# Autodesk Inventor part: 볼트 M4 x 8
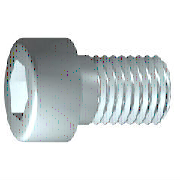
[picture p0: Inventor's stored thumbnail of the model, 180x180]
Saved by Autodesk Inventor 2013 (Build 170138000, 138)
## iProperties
IsCustomPart: 0
Created: 2012-02
Part Number: 볼트 M4 x 8
Material: 스테인리스강
Description: 6각 소켓 머리 캡 나사
Document SubType Name: Modeling
Standard: ISO 4762
Designer: mduedu
Standard Revision: Fourth edition 2004-03-01
Standards Organization: ISO
Language: ko-KR
Size Designation: M4 x 8
Categories: <MemberInstance><Categories><Category DisplayName="조임쇠" InternalName="e4da775c-781d-43d5-af7c-5136215cf5a6" Mnemonic="FSTN"><Category DisplayName="볼트" InternalN
Density: 7.75 g/cm^3
Author: mduedu
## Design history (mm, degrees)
sketch "스케치1"
  geometry: L1 (-1, 0)-(8, 0); L2 (8, 0)-(8, 2); L3 (8, 2)-(1.75, 2); L4 (1.75, 2)-(1.32, 2); L5 (1.32, 2)-(0, 2); L6 (0, 2)-(0, 3.5); L7 (0, 3.5)-(-4, 3.5); L8 (-4, 3.5)-(-4, 1.732); L9 (-4, 1.732)-(-2, 1.732); L10 (-2, 1.732)-(-1, 0); L11 (-6.4, 0)-(10.4, 0) reference; L12 (0, -0.7)-(0, 4.2) reference; L13 (1.75, 2)-(0, 2)
  constraints: 22 end point, 6 parallel, 2 collinear, 2 perpendicular, 1 horizontal, 1 point on line
  dimensions: "d1" = 6.25 distance from line of L3.end L2 (= GEL); "d2" = 0.42952 distance of L4.end L3.end (computed from GAL); "d3" = 4 distance between parallel lines of L8 L6 (= KOH); "d4" = 2 distance of L8.end L9.end (= INTI); "d5" = 60 deg angle of L10 L1; "d6" = 4 diameter of L3 L1 (= GD); "d7" = 4 diameter of L5 L1 (= BDM); "d8" = 3.4641 diameter of L9 L1 (= 1.1547 x SW); "d9" = 7 diameter of L7 L1 (= KOD); "d26" = 8 distance between parallel lines of L12 L2 (= NLG)
revolve "본체" sketch "스케치1" stored, may be unused: angle "d10" = 90 deg
sketch "스케치2"
  geometry: L1 (0, -4.9)-(0, 4.9) reference; L2 (-4.9, 0)-(4.9, 0) reference; L3 (1.732, 0)-(0.866, -1.5); L4 (0.866, -1.5)-(-0.866, -1.5); L5 (-0.866, -1.5)-(-1.732, 0); L6 (-1.732, 0)-(-0.866, 1.5); L7 (-0.866, 1.5)-(0.866, 1.5); L8 (0.866, 1.5)-(1.732, 0); 2 further points
  constraints: 12 end point, 1 coincident, 1 horizontal alignment, 1 point on line, 12 other
extrude "슬롯" join sketch "스케치2" stored distance "d11" = 10; taper "d12" = 0 deg
workplane "Work Plane1"
fillet "Fillet2" dims "d30" = 0.1 (= R)
body "Solid1"
fillet "모깎기1" dims "d17" = 0.4 (= RR)
feature "스레드" dims "d13" = 6.25 (= GEL), "d14" = 0
chamfer "모따기1" distance "d15" = 0.42941 (= -0.5 x SPD + 0.5 x GD); stored, may be unused: second distance "d16" = 0.42941 (= GUL), angle "d27" = 45 deg
other parameters: "GD" = 4 [user parameter; used in 2 equation terms], "NLG" = 8 [user parameter; used in 1 equation term], "GEL" = 6.25 [user parameter; used in 2 equation terms], "KOD" = 7 [user parameter; used in 1 equation term], "KOH" = 4 [user parameter; used in 1 equation term], "INTI" = 2 [user parameter; used in 1 equation term], "GAL" = 0.42941 (= 0.61345 x PTC) [user parameter; used in 1 equation term], "GUL" = 0.42941 (= 0.61345 x PTC) [user parameter; used in 1 equation term], "BDM" = 4 (= NND) [user parameter; used in 1 equation term], "SW" = 3 [user parameter; used in 2 equation terms], "RR" = 0.4 [user parameter; used in 1 equation term], "SPD" = 3.14117 (= NND - 1.2269 x PTC) [user parameter; used in 1 equation term], "d19" = 0, "d28" = 0, "d29" = 0, "R" = 0.1 [user parameter; used in 1 equation term], "TOA" = 30 deg [user parameter], "GD1" = 3.14117 (= THREADDIA - 1.2269 x PTC) [user parameter], "THREADDIA" = 4 [user parameter; used in 1 equation term], "FAWI" = 45 deg [user parameter], "TPU" = 14.28571 (computed from PTC) [user parameter], "PTC" = 0.7 [user parameter; used in 5 equation terms], "NND" = 4 [user parameter; used in 2 equation terms], "E0" = 3.465 (= 1.155 x SW) [user parameter]
